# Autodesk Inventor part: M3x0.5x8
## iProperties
Company: 한국ATC센터
Created: 2009-02
Part Number: M3x0.5x8
Document SubType Name: Modeling
Designer: KYOUNG IL JANG
Density: 7.25 g/cm^3
Mass: 594.644 g
Surface Area: 210.328 cm^2
Volume: 82.0198 cm^3
Material: 주철
Vendor: CBT Solutions
Author: KYOUNG IL JANG
